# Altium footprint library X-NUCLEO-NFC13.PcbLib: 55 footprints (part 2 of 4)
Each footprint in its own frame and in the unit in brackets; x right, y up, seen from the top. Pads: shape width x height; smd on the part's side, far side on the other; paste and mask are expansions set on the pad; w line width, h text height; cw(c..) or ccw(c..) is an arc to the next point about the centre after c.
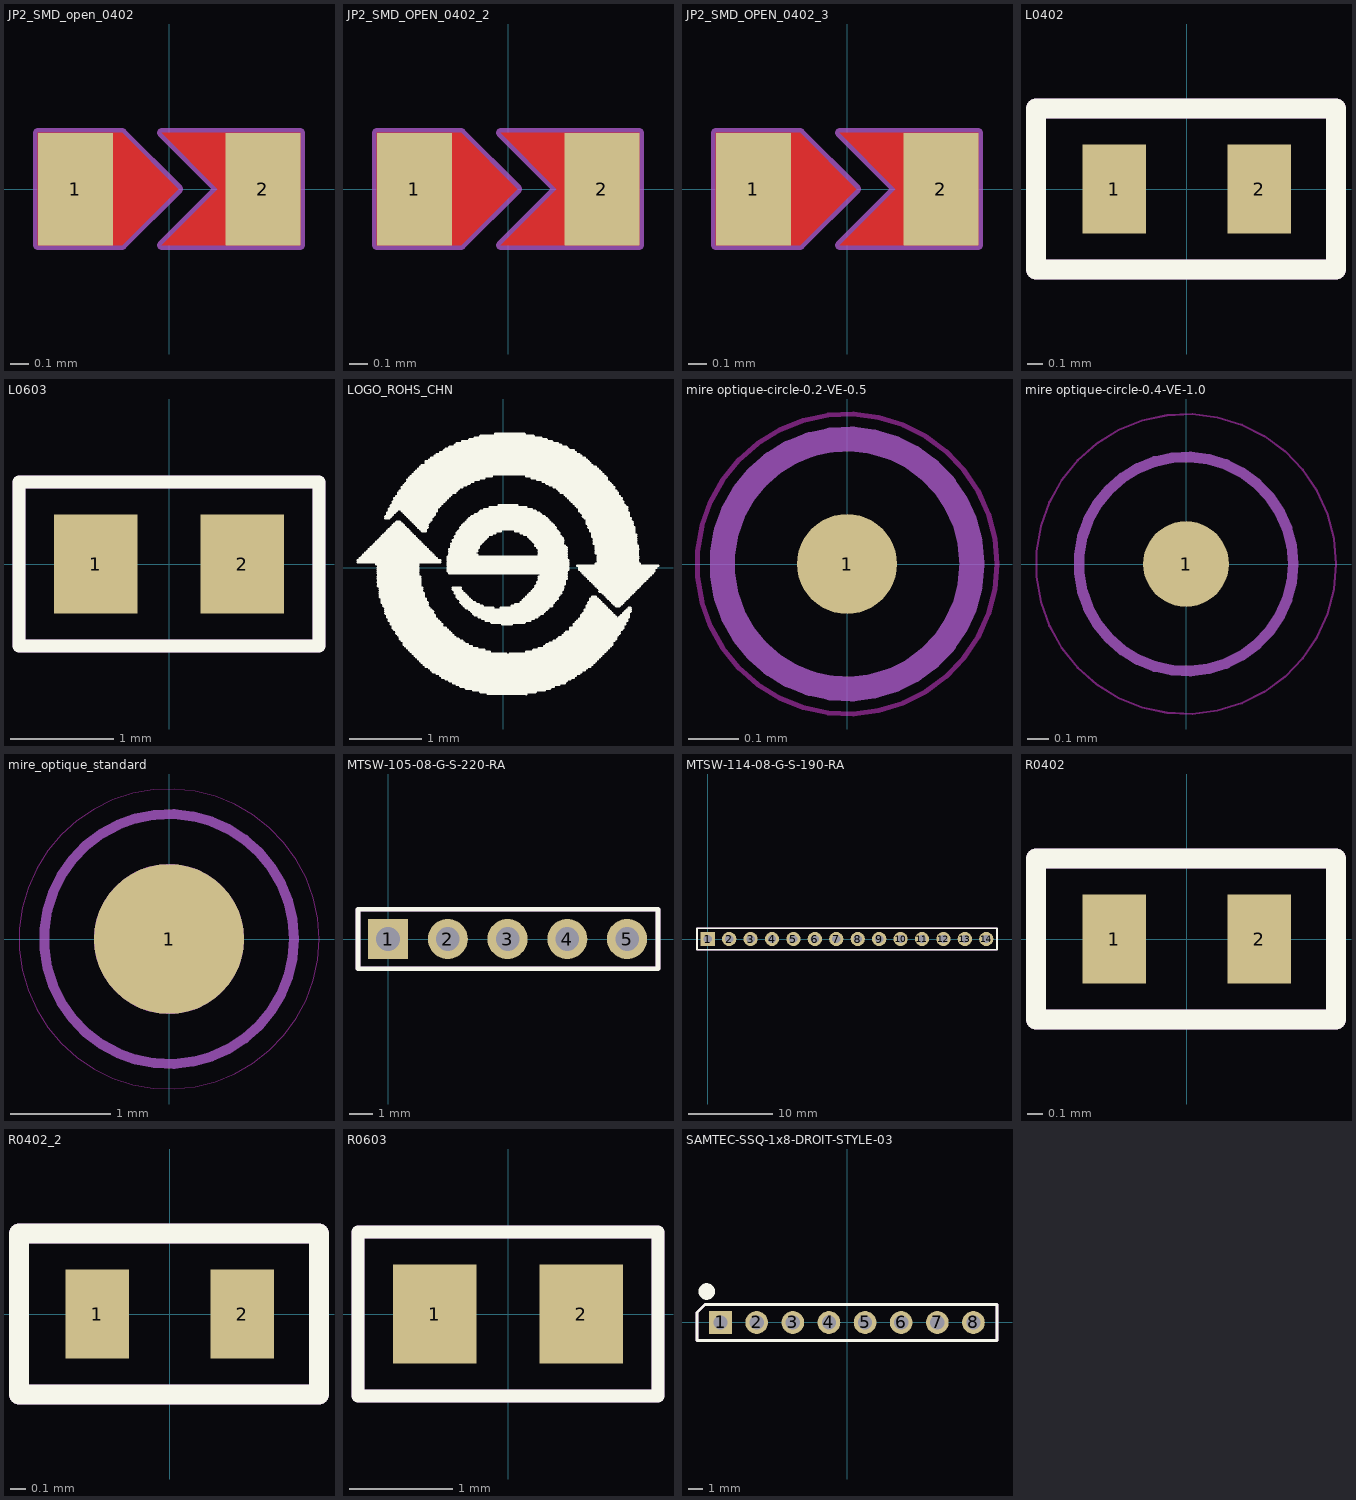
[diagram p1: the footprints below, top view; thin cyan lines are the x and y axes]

## JP2_SMD_open_0402 [mm]
height 2
pads (2):
  rect 0.4x0.6 smd mask+0.05: 1(-0.5,0) 2(0.5,0)
Top Layer:
  region: -0.04,0.3 0.26,0 -0.04,-0.3 0.7,-0.3 0.7,0.3
  region: -0.7,-0.3 -0.7,0.3 -0.25,0.3 0.05,0 -0.25,-0.3
Top Solder:
  rectangle: -0.75,-0.35 0.75,0.35
Top Assembly:
  lines w0.05: -0.7,-0.3 -0.7,0.3 -0.25,0.3 0.05,0 -0.25,-0.3 -0.7,-0.3 ; -0.04,-0.3 0.26,0 -0.04,0.3 0.7,0.3 0.7,-0.3 -0.04,-0.3
  text ".Designator" at -1.363,0.563 h0.6

## JP2_SMD_OPEN_0402_2 [mm]
pads (2):
  rect 0.4x0.6 smd mask+0.05: 1(-0.5,0) 2(0.5,0)
Top Layer:
  region: -0.7,-0.3 -0.7,0.3 -0.25,0.3 0.05,0 -0.25,-0.3
  region: -0.04,0.3 0.26,0 -0.04,-0.3 0.7,-0.3 0.7,0.3
Top Solder:
  rectangle: -0.75,-0.35 0.75,0.35
Top Assembly:
  lines w0.05: -0.7,-0.3 -0.7,0.3 -0.25,0.3 0.05,0 -0.25,-0.3 -0.7,-0.3 ; -0.04,-0.3 0.26,0 -0.04,0.3 0.7,0.3 0.7,-0.3 -0.04,-0.3
  text ".Designator" at -1.363,0.563 h0.6

## JP2_SMD_OPEN_0402_3 [mm]
pads (2):
  rect 0.4x0.6 smd mask+0.05: 1(-0.5,0) 2(0.5,0)
Top Layer:
  region: -0.04,0.3 0.26,0 -0.04,-0.3 0.7,-0.3 0.7,0.3
  region: -0.7,-0.3 -0.7,0.3 -0.25,0.3 0.05,0 -0.25,-0.3
Top Solder:
  rectangle: -0.75,-0.35 0.75,0.35
Top Assembly:
  lines w0.05: -0.7,-0.3 -0.25,-0.3 0.05,0 -0.25,0.3 -0.7,0.3 -0.7,-0.3 ; -0.04,-0.3 0.7,-0.3 0.7,0.3 -0.04,0.3 0.26,0 -0.04,-0.3
  text ".Designator" at -1.363,0.563 h0.6

## L0402 [mil]
height 23.62
pads (2):
  rect 15.75x22 smd paste+0 mask+0: 1(-18,0) 2(18,0)
Top Overlay:
  lines w5: -37.42,-20 37,-20 37,20 -37.42,20 -37.42,-20
Top Assembly:
  lines w5: -37.42,-20 37,-20 37,20 -37.42,20 -37.42,-20
  text ".Designator" at -62.18,31.53 h23.62
3D body: height 11.81, standoff 0, extent 22,-11 27,11
3D body: height 11.81, standoff 0, extent -22,-11 22,11
3D body: height 11.81, standoff 0, extent -26.87,-11 -22,11

## L0603 [mil]
pads (2):
  rect 32x38 smd paste+0 mask+0: 1(-28,0) 2(28,0)
Top Overlay:
  lines w5: -57.5,-31.5 -57.5,31.5 57.5,31.5 57.5,-31.5 -57.5,-31.5
Top Assembly:
  lines w5: -57.5,-31.5 -57.5,31.5 57.5,31.5 57.5,-31.5 -57.5,-31.5
  text ".Designator" at -66.87,41.37 h23.62
3D body: height 20, standoff 0, extent -38.43,-18.95 -30.56,19.05
3D body: height 20, standoff 0, extent 32.43,-18.95 40.31,19.05
3D body: height 20, standoff 0, extent -30.56,-18.95 32.43,19.05

## LOGO_ROHS_CHN [mm] "Silk only"
Top Overlay:
  drawing of 356 lines, arcs and shapes, not listed

## mire optique-circle-0.2-VE-0.5 [mm]
pads (1):
  round 0.2 smd: 1(0,0)
Top Layer keep-out:
  circle w0.01: c0,0 r0.3
Top Solder:
  circle w0.25: c0,0 r0.125
Top Assembly:
  circle w0.05: c0,0 r0.25
  text ".Designator" at -1.7,0.75 h1

## mire optique-circle-0.4-VE-1.0 [mm]
pads (1):
  round 0.4 smd: 1(0,0)
Top Layer keep-out:
  circle w0.01: c0,0 r0.7
Top Solder:
  circle w0.5: c0,0 r0.25
Top Assembly:
  circle w0.05: c0,0 r0.5
  text ".Designator" at -1.7,0.75 h1

## mire_optique_standard [mm]
pads (1):
  round 1.5 smd mask+0.5: 1(0,0)
Top Layer keep-out:
  circle w0.01: c0,0 r1.5
Top Solder:
  region: 0,-1.27 -0.167,-1.27 -0.49,-1.183 -0.78,-1.016 -1.016,-0.78 -1.183,-0.49 -1.27,-0.167 -1.27,0.167 -1.183,0.49 -1.016,0.78 -0.78,1.016 -0.49,1.183 -0.167,1.27 0,1.27 0.167,1.27 0.49,1.183 0.78,1.016 1.016,0.78 1.183,0.49 1.27,0.167 1.27,-0.167 1.183,-0.49 1.016,-0.78 0.78,-1.016 0.49,-1.183 0.167,-1.27
Top Assembly:
  circle w0.75: c0,0 r0.375
  circle w0.1: c0,0 r1.25
  text ".Designator" at -1.397,1.778 h1

## MTSW-105-08-G-S-220-RA [mm] "5 Pin header 90deg"
height 3.09
pads (5):
  rect 1.7x1.7 hole 1: 1(0,0)
  round 1.7 hole 1: 2(2.54,0) 3(5.08,0) 4(7.62,0) 5(10.16,0)
Top Overlay:
  lines w0.2: -1.275,-1.27 -1.275,1.27 11.475,1.27 11.475,-1.27 -1.275,-1.27
Top Assembly:
  lines w0.2: -1.275,-1.27 -1.275,1.27 11.475,1.27 11.475,-1.27 -1.275,-1.27
  text ".Designator" at 2.297,-2.076 h0.6
3D body "TSW-105-08-G-S-NA.stp": height 2.77, standoff -2.54, extent -1.25,-0.3 11.577,9.923

## MTSW-114-08-G-S-190-RA [mm] "14 Pin header 90deg"
height 3.09
pads (14):
  rect 1.7x1.7 hole 1: 1(0,0)
  round 1.7 hole 1: 2(2.54,0) 3(5.08,0) 4(7.62,0) 5(10.16,0) 6(12.7,0) 7(15.24,0) 8(17.78,0) 9(20.32,0) 10(22.86,0) 11(25.4,0) 12(27.94,0) 13(30.48,0) 14(33.02,0)
Top Overlay:
  lines w0.2: -1.27,-1.27 -1.27,1.27 34.29,1.27 34.29,-1.27 -1.27,-1.27
Top Assembly:
  lines w0.2: -1.27,-1.27 -1.27,1.27 34.29,1.27 34.29,-1.27 -1.27,-1.27
  text ".Designator" at 13.797,-2.326 h0.6
3D body "TSW-114-08-G-S-NA.stp": height 2.77, standoff -2.54, extent -1.28,-0.316 34.407,9.907

## PCBComponent_1 [mm]

## R0402 [mil]
pads (2):
  rect 15.75x22 smd paste+0 mask+0: 1(-18,0) 2(18,0)
Top Overlay:
  lines w5: -37.42,-20 -37.42,20 37,20 37,-20 -37.42,-20
Top Assembly:
  lines w5: -37.42,-20 -37.42,20 37,20 37,-20 -37.42,-20
  text ".Designator" at -47.18,31.53 h23.62
3D body: height 11.81, standoff 0, extent -22,-11 22,11
3D body: height 11.81, standoff 0, extent 22,-11 27,11
3D body: height 11.81, standoff 0, extent -26.87,-11 -22,11

## R0402_2 [mil]
pads (2):
  rect 15.75x22 smd paste+0 mask+0: 1(-18,0) 2(18,0)
Top Overlay:
  lines w5: -37.42,-20 -37.42,20 37,20 37,-20 -37.42,-20
Top Assembly:
  lines w5: -37.42,-20 -37.42,20 37,20 37,-20 -37.42,-20
  text ".Designator" at -47.18,31.53 h23.62
3D body: height 11.81, standoff 0, extent -26.87,-11 -22,11
3D body: height 11.81, standoff 0, extent 22,-11 27,11
3D body: height 11.81, standoff 0, extent -22,-11 22,11

## R0603 [mil]
pads (2):
  rect 32x38 smd paste+0 mask+0: 1(-28,0) 2(28,0)
Top Overlay:
  lines w5: -57.5,-31.5 57.5,-31.5 57.5,31.5 -57.5,31.5 -57.5,-31.5
Top Assembly:
  lines w5: -57.5,-31.5 57.5,-31.5 57.5,31.5 -57.5,31.5 -57.5,-31.5
  text ".Designator" at -66.87,41.37 h23.62
3D body: height 20, standoff 0, extent -38.43,-18.95 -30.56,19.05
3D body: height 20, standoff 0, extent 32.43,-18.95 40.31,19.05
3D body: height 20, standoff 0, extent -30.56,-18.95 32.43,19.05

## SAMTEC-SSQ-1x8-DROIT-STYLE-03 [mm]
pads (8):
  rect 1.6x1.6 hole 1: 1(-8.89,0)
  round 1.6 hole 1: 2(-6.35,0) 3(-3.81,0) 4(-1.27,0) 5(1.27,0) 6(3.81,0) 7(6.35,0) 8(8.89,0)
Top Overlay:
  circle w0.6: c-9.86,2.18 r0.284
  lines w0.2: -10.55,-1.27 10.55,-1.27 10.55,1.27 -9.99,1.27 -10.55,0.71 -10.55,-1.27
Top Assembly:
  lines w0.2: -10.55,-1.27 10.55,-1.27 10.55,1.27 -9.99,1.27 -10.55,0.71 -10.55,-1.27
  text "1" at -9.044,-0.545 h1.05
  text ".Designator" at -14.005,-0.525 h1.05
3D body "SSQ-108-03-L-S.stp": height 8.51, standoff -10.01, extent -10.414,-1.207 10.414,1.206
